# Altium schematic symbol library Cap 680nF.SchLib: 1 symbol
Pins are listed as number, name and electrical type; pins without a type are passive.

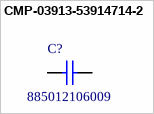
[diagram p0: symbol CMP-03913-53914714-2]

## CMP-03913-53914714-2
designator C?, comment 885012106009
Cap Cer 0.68UF 10V X5R 0603; Tolerance: 20%; Insulation Resistance: 200MΩ; Capacitance: 680nF
footprint WCAP-CSGP_0603_L1.6W0.8H0.8_Reflow (Ceramic Capacitors, body 1.6x0.8mm)
pins: 1, 2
